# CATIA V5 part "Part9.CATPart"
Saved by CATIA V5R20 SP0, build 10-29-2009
Part number: Part9
Bounding box of the stored display mesh (mm): x -1500 to 1500, y -1500 to 1900, z 200 to 2270
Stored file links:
  E:\新建文件夹 (2)\Part9.CATPart
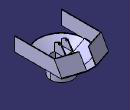
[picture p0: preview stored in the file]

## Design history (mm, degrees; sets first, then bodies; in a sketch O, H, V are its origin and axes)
Body1 (main body)
  Plane1: type Offset, RefPlane xy-plane, Offset 1400
  Plane2: type Offset, RefPlane xy-plane, Offset 1000
  Sketch1 on Plane1, origin (0, 0, 1400), H (1, 0, 0), V (0, 1, 0)
    circle A1 centre (0, 0) radius 1500
    point P1 (0, 1500)
    radius A1 = 1500
    coincidence: A1 P1, P1 V
  Sketch2 on Plane2, origin (0, 0, 1000), H (1, 0, 0), V (0, 1, 0)
    circle A1 centre (0, 0) radius 700
    point P1 (0, 700)
    coincidence: A1 P1, P1 V
  Pad1: profile Sketch2, direction (0, 0, -1), length 800, thin wall 40
  Plane3: type Offset, RefPlane xy-plane, Offset 200
  Sketch3 on Plane3, origin (0, 0, 200), H (1, 0, 0), V (0, 1, 0)
    circle A1 centre (0, 0) radius 700
    point P1 (0, 700)
    coincidence: A1 P1, P1 V
  Pad2: profile Sketch3, direction (0, 0, 1), length 40
  Loft1: solid, Sections (Sketch1; edge [face of Pad2 | start face of Pad1])
  Body2
    Plane4: type Offset, RefPlane xy-plane, Offset 1000
    Plane5: type Offset, RefPlane xy-plane, Offset 1400
    Sketch4 on Plane4, origin (0, 0, 1000), H (1, 0, 0), V (0, 1, 0)
      circle A1 centre (0, 0) radius 660
      point P1 (0, 660)
      coincidence: A1 P1, P1 V
    Sketch5 on Plane5, origin (0, 0, 1400), H (1, 0, 0), V (0, 1, 0)
      circle A1 centre (0, 0) radius 1460
      point P1 (0, 1460)
      coincidence: A1 P1, P1 V
    Loft2: solid, Sections (Sketch4; Sketch5)
  Remove1: tool Body2
  Sketch6 on end face of Pad2, origin (0, 0, 240), H (1, 0, 0), V (0, 1, 0)
    line L1 (200, 200) -> (200, -200)
    line L2 (200, -200) -> (-200, -200)
    line L3 (-200, -200) -> (-200, 200)
    line L4 (-200, 200) -> (200, 200)
    vertical: L1 V, L3 V
    horizontal: L2 H, L4 H
    equidistance: L1 L3 O, L2 L4 O
  Pad3: profile Sketch6, direction (0, 0, 1), length 1200
  Plane6: type Offset, RefPlane Plane5, Offset 420
  Sketch7 on end face of Pad3, origin (0, 0, 1440), H (1, 0, 0), V (0, 1, 0)
    point P1 (0, 0)
    line L1 (250, 500) -> (250, -200)
    line L2 (-250, -200) -> (-250, 500)
    line L3 (-250, 500) -> (250, 500)
    line L4 (250, -200) -> (-250, -200)
    coincidence: P1 V, P1 O
    vertical: L1 V, L2 V
    horizontal: L3 H, L4 H
    equidistance: L1 L2 P1
  Pad4: profile Sketch7, direction (0, 0, 1), length 120
  Sketch8 on end face of Pad4, origin (0, 0, 1560), H (1, 0, 0), V (0, 1, 0)
    point P1 (-225, -100)
    line L1 (-200, 0) -> (-200, -200)
    line L2 (-200, -200) -> (-250, -200)
    line L3 (-250, -200) -> (-250, 0)
    line L4 (-250, 0) -> (-200, 0)
    point P5 (-250, 0)
    point P6 (225, -100)
    line L5 (250, 0) -> (250, -200)
    line L6 (250, -200) -> (200, -200)
    line L7 (200, -200) -> (200, 0)
    line L8 (200, 0) -> (250, 0)
    point P7 (250, 0)
    vertical: L1 V, L3 V, L5 V, L7 V
    horizontal: L2 H, L4 H, L6 H, L8 H
    equidistance: L1 L3 P1, L2 L4 P1, L5 L7 P6, L6 L8 P6
    coincidence: P5 H, P7 H
  Pad5: profile Sketch8, direction (0, 0, 1), length 380
  Sketch9 on face of Pad5, origin (250, 0, 0), H (0, 1, 0), V (0, 0, 1)
    circle A1 centre (100, 2000) radius 50
    arc A2 centre (100, 2000) radius 87.0071 from (172.2508, 2048.4774) to (59.3775, 2076.9419) ccw
    point P2 (0, 1940)
    reference projected point E1 (0, 1940) from vertex [face of Pad5 from Sketch8.L5 | face of Pad5 from Sketch8.L8 | end face of Pad5]
    line L1 (200, 1560) -> (400, 1560)
    line L2 (-200, 1940) -> (59.3775, 2076.9419)
    line L3 (-200, 1940) -> (0, 1940)
    line L4 (0, 1940) -> (0, 1560)
    point P9 (0, 1560)
    line L5 (0, 1560) -> (200, 1560)
    line L6 (400, 1560) -> (500, 1560)
    point P10 (400, 1560)
    line L7 (500, 1560) -> (172.2508, 2048.4774)
    distance P2 E1 = 0
    horizontal: L1 H, L3 H, L5 H, L6 H
    tangency: L2 A2, L7 A2
    coincidence: P9 L1, P10 L5
    vertical: L4 V
  Pad6: profile Sketch9, direction (-1, 0, 0), length 50
  Sketch10 on face of Pad5, origin (-250, 0, 0), H (0, -1, 0), V (0, 0, 1)
    circle A1 centre (-100, 2000) radius 50
    arc A2 centre (-100, 2000) radius 87.0071 from (-59.3775, 2076.9419) to (-172.2508, 2048.4774) ccw
    reference projected arc E1 centre (-100, 2000) radius 87.0071 from (-59.3775, 2076.9419) to (-172.2508, 2048.4774) ccw from edge [end face of Pad6 | face of Pad6 from Sketch9.A2]
    line L1 (200, 1940) -> (-59.3775, 2076.9419)
    line L2 (200, 1940) -> (0, 1940)
    point P4 (0, 1940)
    line L3 (0, 1560) -> (0, 1940)
    point P5 (0, 1560)
    line L4 (0, 1560) -> (-500, 1560)
    line L5 (-500, 1560) -> (-172.2508, 2048.4774)
    coincidence: A2 E1, P4 V, P5 V
    tangency: L1 A2, L5 A2
    horizontal: L2 H, L4 H
    vertical: L3 V
  Pad7: profile Sketch10, direction (1, 0, 0), length 50
  Sketch11 on face of Loft1, origin (0, 0, 1400), H (1, 0, 0), V (0, 1, 0)
    line L1 (1500, 1500) -> (1500, -1500)
    line L2 (-1500, -1500) -> (-1500, 1500)
    line L3 (1460, 0) -> (1460, -1460)
    line L4 (-1460, -1460) -> (-1460, 0)
    arc A1 centre (0, 0) radius 1460 from (1460, 0) to (-1460, 0) ccw
    point P7 (0, 1460)
    line L5 (-1500, 1500) -> (-300, 1900)
    line L6 (1500, 1500) -> (300, 1900)
    point P8 (0, 1500)
    line L7 (0, 1900) -> (-300, 1900)
    line L8 (0, 1900) -> (300, 1900)
    line L9 (-1500, -1500) -> (-1460, -1460)
    line L10 (1500, -1500) -> (1460, -1460)
    vertical: L1 V, L2 V, L3 V, L4 V
    equidistance: L1 L2 O, L3 L4 O
    coincidence: A1 P7, P7 V, L9 O, L10 O
    horizontal: L7 H, L8 H
  Pad8: profile Sketch11, direction (0, 0, 1), length 50
  Plane7: type Offset, RefPlane Plane6, Offset 450
  Sketch12 on end face of Pad8, origin (0, 0, 1450), H (1, 0, 0), V (0, 1, 0)
    line L1 (-1500, 1500) -> (-300, 1900)
    point P1 (-1500, 1500)
    point P2 (-300, 1900)
    reference projected point E1 (-1500, 1500) from vertex [face of Pad8 from Sketch11.L5 | face of Pad8 from Sketch11.L2 | end face of Pad8]
    reference projected point E2 (-300, 1900) from vertex [face of Pad8 from Sketch11.L7 | face of Pad8 from Sketch11.L5 | end face of Pad8]
    line L2 (1500, 1500) -> (300, 1900)
    point P3 (1500, 1500)
    point P4 (300, 1900)
    reference projected point E3 (300, 1900) from vertex [face of Pad8 from Sketch11.L8 | end face of Pad8 | face of Pad8 from Sketch11.L6]
    reference projected point E4 (1500, 1500) from vertex [face of Pad8 from Sketch11.L1 | end face of Pad8 | face of Pad8 from Sketch11.L6]
    line L3 (-1500, 1500) -> (-1500, -1500)
    point P5 (-1500, -1500)
    reference projected point E5 (-1500, -1500) from vertex [face of Pad8 from Sketch11.L2 | face of Pad8 from Sketch11.L9 | end face of Pad8]
    line L4 (1500, 1500) -> (1500, -1500)
    point P6 (1500, -1500)
    line L5 (-1500, -1500) -> (-1460, -1460)
    line L6 (1500, -1500) -> (1460, -1460)
    point P9 (-1500, 0)
    line L7 (-1460, 1471.1696) -> (-300, 1857.8363)
    line L8 (-300, 1900) -> (-173.5089, 1900)
    line L9 (-1460, -1460) -> (-1460, 1471.1696)
    line L10 (300, 1857.8363) -> (1460, 1471.1696)
    line L11 (300, 1900) -> (173.5089, 1900)
    line L12 (1460, -1460) -> (1460, 1471.1696)
    line L13 (300, 1857.8363) -> (-300, 1857.8363)
    line L14 (-173.5089, 1900) -> (173.5089, 1900)
    length L13 = 600
    length L4 = 3000
    distance P6 L14 = 3400
    distance L10 L2 = 40
    coincidence: P1 E1, P2 E2, E3 P4, P3 E4, E5 P5, L5 O
    perpendicularity: L6 L5
    midpoint: P9 L3
    horizontal: L8 H, L11 H
  Sketch13 on Plane7, origin (0, 0, 2270), H (1, 0, 0), V (0, 1, 0)
    line L1 (-1500, 1038.9751) -> (-173.5089, 1481.1388)
    reference projected arc E1 centre (0, 0) radius 1460 from (1460, 0) to (-1460, 0) ccw from edge [face of Pad8 from Sketch11.A1 | end face of Pad8]
    line L2 (-1460, 1010.1448) -> (-173.5089, 1438.9751)
    line L3 (-1500, -1500) -> (-1500, 1038.9751)
    line L4 (-1500, -1500) -> (-1460, -1460)
    line L5 (-1460, -1460) -> (-1460, 1010.1448)
    line L6 (173.5089, 1481.1388) -> (1500, 1038.9751)
    reference projected arc E2 centre (0, 0) radius 1460 from (1460, 0) to (-1460, 0) ccw from edge [face of Pad8 from Sketch11.A1 | end face of Pad8]
    line L7 (1500, -1500) -> (1500, 1038.9751)
    line L8 (1500, -1500) -> (1460, -1460)
    line L9 (1460, -1460) -> (1460, 1010.1448)
    point P11 (1460, -1460)
    line L10 (173.5089, 1438.9751) -> (1460, 1010.1448)
    line L11 (-173.5089, 1481.1388) -> (173.5089, 1481.1388)
    line L12 (-173.5089, 1438.9751) -> (173.5089, 1438.9751)
    point P14 (-1154.2313, 1154.2313)
    point P15 (-1122.6086, 1122.6086)
    distance L10 L6 = 40
    distance L7 L3 = 3000
    tangency: L1 E1, L6 E2
    perpendicularity: L8 L4
    coincidence: P11 L8, P14 L8, P14 L1, P15 L8, P15 L2
  Loft3: solid, Sections (Sketch12; Sketch13)
  Body3
    Plane8: type Offset, RefPlane xy-plane, Offset 1450
    Plane9: type Offset, RefPlane Plane8, Offset 820
    Sketch14 on Plane9, origin (0, 0, 2270), H (1, 0, 0), V (0, 1, 0)
      line L1 (300, 1496.8114) -> (300, 1396.8114)
      line L2 (-300, 1496.8114) -> (-300, 1396.8114)
      line L3 (-300, 1496.8114) -> (300, 1496.8114)
      line L4 (-300, 1396.8114) -> (300, 1396.8114)
      distance L4 L3 = 100
      vertical: L1 V, L2 V
      horizontal: L3 H, L4 H
    Sketch15 on Plane8, origin (0, 0, 1450), H (1, 0, 0), V (0, 1, 0)
      line L1 (300, 1900) -> (-300, 1900)
      line L2 (300, 1900) -> (300, 1857.8363)
      line L3 (300, 1857.8363) -> (-300, 1857.8363)
      line L4 (-300, 1900) -> (-300, 1857.8363)
      horizontal: L1 H, L3 H
      vertical: L2 V, L4 V
    Loft4: solid, Sections (Sketch14; Sketch15)
  Remove2: tool Body3
  Sketch16 on end face of Pad2, origin (0, 0, 240), H (1, 0, 0), V (0, 1, 0)
    circle A1 centre (550, 0) radius 64
    circle A2 centre (0, 0) radius 660
    point P2 (0, 660)
    circle A3 centre (0, 0) radius 440
    point P3 (440, 0)
    circle A4 centre (0, 550) radius 64
    point P5 (0, 614)
    point P7 (-486, 0)
    circle A5 centre (-550, 0) radius 64
    circle A6 centre (0, -550) radius 64
    point P8 (0, -550)
    circle A7 centre (388.9087, 388.9087) radius 64
    circle A8 centre (210.4759, 508.1337) radius 64
    circle A9 centre (508.1337, 210.4759) radius 64
    circle A10 centre (-508.1337, -210.4759) radius 64
    circle A11 centre (210.4759, -508.1337) radius 64
    circle A12 centre (-508.1337, 210.4759) radius 64
    circle A13 centre (-388.9087, 388.9087) radius 64
    circle A14 centre (388.9087, -388.9087) radius 64
    circle A15 centre (508.1337, -210.4759) radius 64
    circle A16 centre (-388.9087, -388.9087) radius 64
    circle A17 centre (-210.4759, -508.1337) radius 64
    circle A18 centre (-210.4759, 508.1337) radius 64
    coincidence: A4 P5, A5 P7, P8 V
  Pad9: profile Sketch16, direction (0, 0, 1), length 100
